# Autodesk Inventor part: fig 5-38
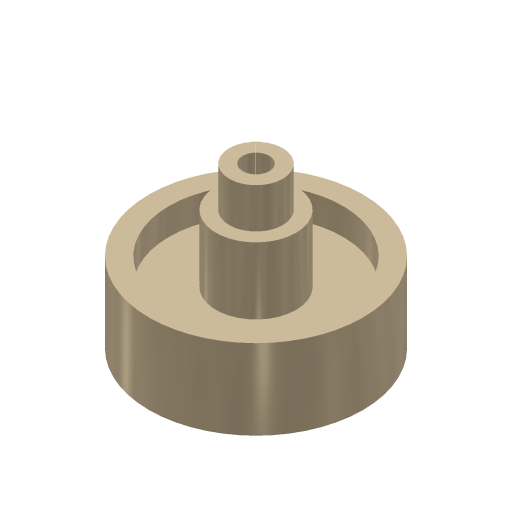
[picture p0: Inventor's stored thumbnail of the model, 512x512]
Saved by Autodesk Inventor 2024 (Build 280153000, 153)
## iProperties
Created: 2001-11
Part Number: fig 5-38
Document SubType Name: Modeling
Designer: Renu Muthoo
Density: 1 g/cm^3
Material: Generic
Appearance: Metal-Titanium (Polished)
Control State: 0
Master: False
Checked Out: False
Shininess: 65.0
Length Units: 11269
Angle Units: 11279
Time Units: 11290
Mass Units: 11283
Length Display Precision: 3
Angle Display Precision: 2
Density: 0.0
Volumn: 0.0
Area: 0.0
PropertySet Name: Model Information
Author: Renu Muthoo
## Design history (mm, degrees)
sketch "Sketch1"
  geometry: L1 (2.694, 30.112)-(5.194, 30.112); L2 (5.194, 30.112)-(5.194, 22.612); L3 (5.194, 22.612)-(7.694, 22.612); L4 (7.694, 22.612)-(7.694, 10.112); L5 (7.694, 10.112)-(16.444, 10.112); L6 (16.444, 10.112)-(16.444, 15.112); L7 (16.444, 15.112)-(20.194, 15.112); L8 (0.194, -4.034)-(0.194, 25.966); L9 (2.694, 30.112)-(2.694, 0.112); L10 (2.694, 0.112)-(20.194, 0.112); L11 (20.194, 0.112)-(20.194, 15.112)
  constraints: 22 end point, 7 parallel, 2 perpendicular, 1 horizontal
  dimensions: "d0" = 5 diameter of L9 L8; "d1" = 10 diameter of L2 L8; "d2" = 15 diameter of L4 L8; "d3" = 32.5 diameter of L6 L8; "d4" = 40 diameter of L11 L8; "d5" = 15 distance of L10.end L7.end; "d6" = 22.5 distance between parallel lines of L3 L10; "d7" = 30 distance between parallel lines of L1 L10; "d8" = 10 distance between parallel lines of L10 L5
revolve "Revolution1" sketch "Sketch1" stored, may be unused: angle "d9" = 90 deg
workaxis "Work Axis1"
workaxis "Work Axis4"
body "Solid1"
node "Sketch3"
